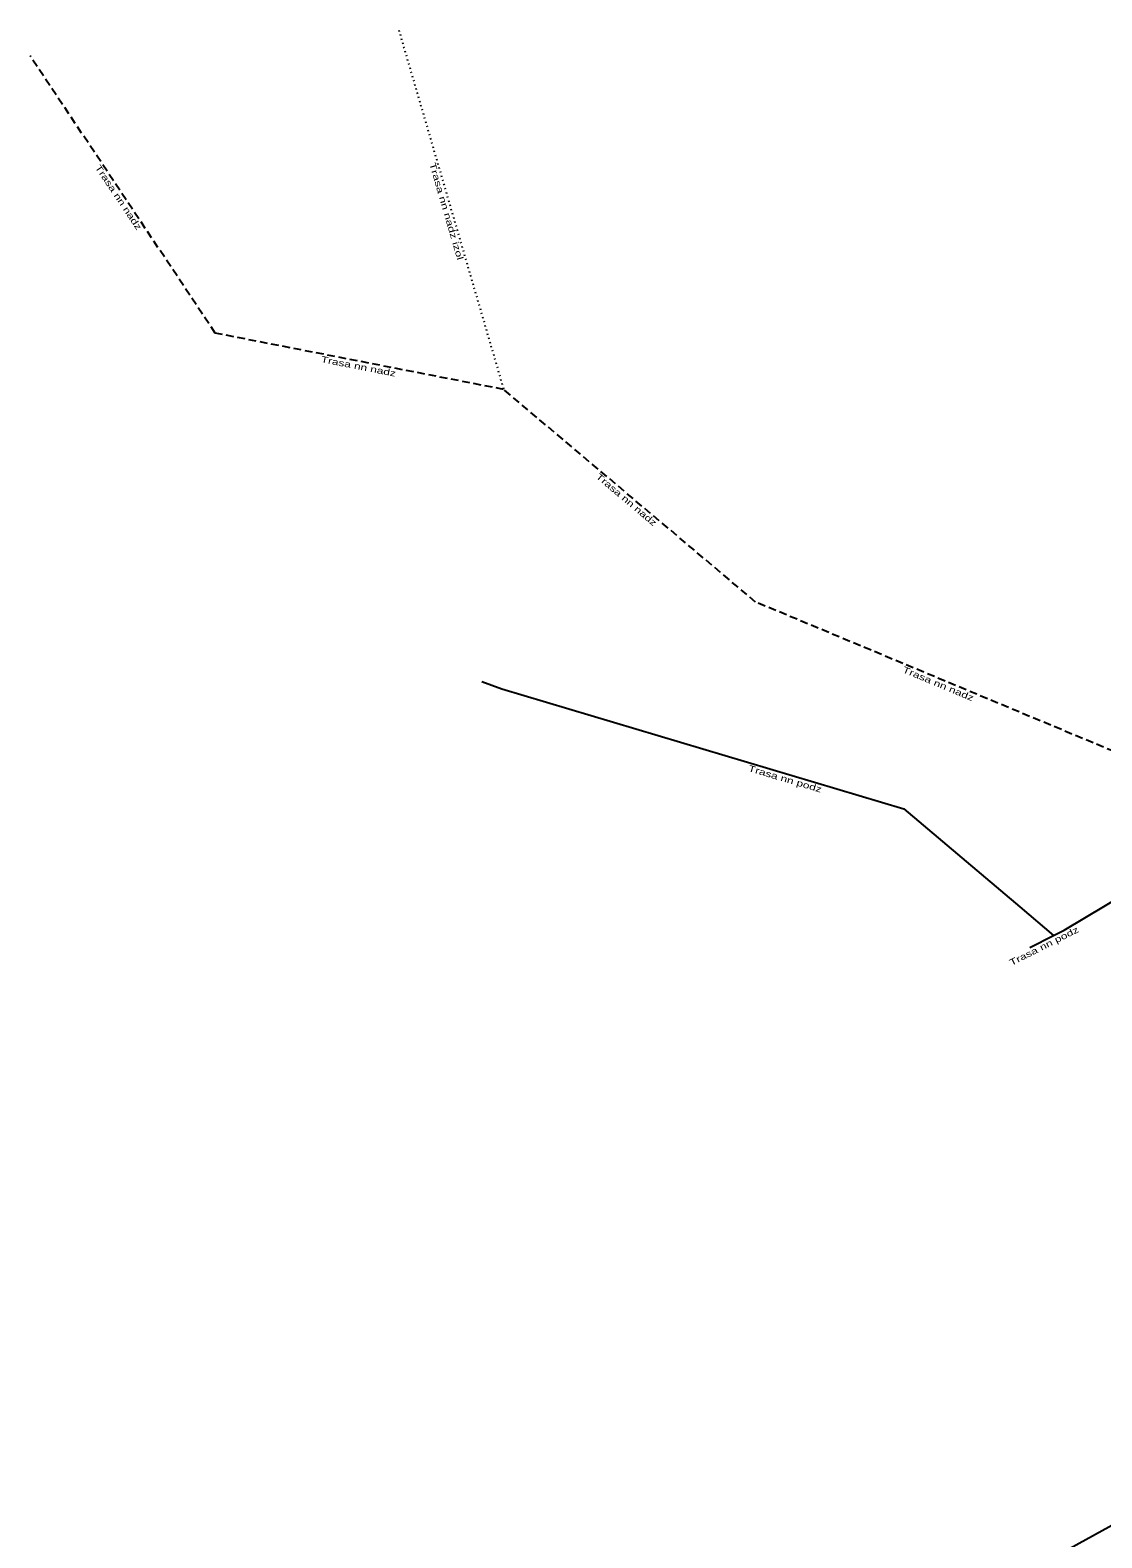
# Model space of a CAD drawing. Extents: x -733620 to -732615, y -1025255 to -1024617.
# Drawn here: x -733319.4 to -733235.2, y -1024903.7 to -1024785.3 of the extents above; entities that cross this region are included whole.
import ezdxf
from ezdxf.enums import TextEntityAlignment as Align

# ---------------------------------------------------------------- set-up
doc = ezdxf.new("R2010")
doc.units = 0
doc.header["$LTSCALE"] = 0.2
doc.linetypes.add('DOTTED', pattern=[1.5, 0.3, -1.2])
doc.linetypes.add('MEDIUM_DASHED', pattern=[4.5, 3, -1.5])
doc.layers.add('11', color=7, linetype='MEDIUM_DASHED', lineweight=25)
doc.layers.add('20', color=7, linetype='Continuous')

msp = doc.modelspace()

# ---------------------------------------------------------------- linework, layer by layer
at = {"layer": '11', "linetype": 'DOTTED'}
msp.add_line((-733290.436, -1024785.277), (-733282.2, -1024813.5), dxfattribs=at)
at = {"layer": '11'}
for p, q in [((-733304.858, -1024809.078), (-733319.4, -1024787.3)), ((-733282.2, -1024813.5), (-733304.858, -1024809.078)), ((-733262.4, -1024830.2), (-733282.2, -1024813.5)), ((-733233.4, -1024842.3), (-733262.4, -1024830.2))]:
    msp.add_line(p, q, dxfattribs=at)
at = {"layer": '11', "linetype": 'Continuous'}
msp.add_line((-733240.86, -1024857.33), (-733238.99, -1024856.39), dxfattribs=at)
for points in [[(-733283.92, -1024836.45), (-733282.35, -1024837.03), (-733250.76, -1024846.45), (-733241.65, -1024854.15), (-733238.99, -1024856.39)], [(-733238.99, -1024856.39), (-733238.15, -1024855.97), (-733228.55, -1024850.23), (-733225.98, -1024851.32), (-733213.53, -1024857.58), (-733206.78, -1024861.02), (-733190.83, -1024868.98), (-733189.45, -1024871.27), (-733188.81, -1024874.06), (-733189.33, -1024876.13), (-733189.59, -1024877.07), (-733191.48, -1024879.15)], [(-733281.31, -1024929.64), (-733260.86, -1024917.5), (-733241.06, -1024906.39), (-733223.38, -1024896.65), (-733210.88, -1024889.72)]]:
    msp.add_lwpolyline(points, dxfattribs=at)

# ---------------------------------------------------------------- texts
at = {"layer": '20'}
for s, rotation, width, p in [('Trasa nn nadz', 303.733, 1.4, (-733312.6691, -1024798.5497)), ('Trasa nn nadz izol', 286.268, 1.45, (-733286.9409, -1024799.5705)), ('Trasa nn nadz', 348.956, 1.4, (-733293.6534, -1024811.9263)), ('Trasa nn nadz', 319.855, 1.4, (-733272.7187, -1024822.347)), ('Trasa nn nadz', 337.352, 1.4, (-733248.1498, -1024836.8495)), ('Trasa nn podz', 343.396, 1.4, (-733260.1609, -1024844.3242)), ('Trasa nn podz', 26.687, 1.4, (-733239.6328, -1024857.4404))]:
    msp.add_text(s, height=0.5, rotation=rotation, dxfattribs=dict(at, width=width)).set_placement(p, align=Align.CENTER)

doc.saveas('drawing.dxf')
